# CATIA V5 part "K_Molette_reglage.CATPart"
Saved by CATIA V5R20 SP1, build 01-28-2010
Part number: molette_reglage
Bounding box of the stored display mesh (mm): x -15.5 to 15.5, y -15.5 to 15.5, z -39.628 to 0
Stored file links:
  G:\Khaled_CFAO_2011\SIL\SIL_GR1\mroland\Khaled\CAD_CATIA_Modifie\K_Molette_reglage.CATPart
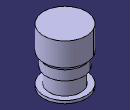
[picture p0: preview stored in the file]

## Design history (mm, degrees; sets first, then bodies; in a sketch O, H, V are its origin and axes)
Set1
  Sketch1 on yz-plane, origin (0, 0, 0), H (0, 1, 0), V (0, 0, 1)
    point P1 (0, 0)
    line L1 (0, 0) -> (15.5, 0)
    line L2 (15.5, 0) -> (15.5, 0)
    point P3 (15.5, 0)
    line L3 (13.5, -19.6283) -> (13.5, -26.6283)
    line L4 (13.5, -26.6283) -> (11.5, -26.6283)
    line L5 (11.5, -26.6283) -> (11.5, -37.6283)
    line L6 (11.5, -37.6283) -> (15.5, -37.6283)
    point P8 (15.5, -37.6283)
    line L7 (15.5, -37.6283) -> (15.5, -39.6283)
    line L8 (15.5, -39.6283) -> (8.5, -39.6283)
    line L9 (8.5, -39.6283) -> (8.5, -26.6283)
    point P11 (8.5, -26.6283)
    line L10 (8.5, -26.6283) -> (7, -26.6283)
    line L11 (7, -26.6283) -> (7, -2.8819)
    line L12 (0, 0) -> (0, -2)
    line L13 (0, -2) -> (7, -2.8819)
    line L14 (15.5, 0) -> (15.5, -17)
    line L15 (15.5, -17) -> (13.5, -19.6283)
    length L12 = 2
    distance L11 L12 = 7
    length L14 = 17
    length L3 = 7
    length L9 = 13
    length L8 = 7
    length L5 = 11
    length L10 = 1.5
    length L7 = 2
    length L4 = 2
    length L15 = 3.3027
    length L6 = 4
    coincidence: P1 V, P3 H, P8 L2, P11 L4, O P1
    horizontal: L1 H, L4 H, L8 H, L10 H
    vertical: L2 V, L3 V, L5 V, L7 V, L9 V, L11 V, L12 V, L14 V
    perpendicularity: L4 L5, L10 L9, L8 L7
Body1 (main body)
  Shaft1: profile Sketch1, axis Sketch1.V, angle 360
